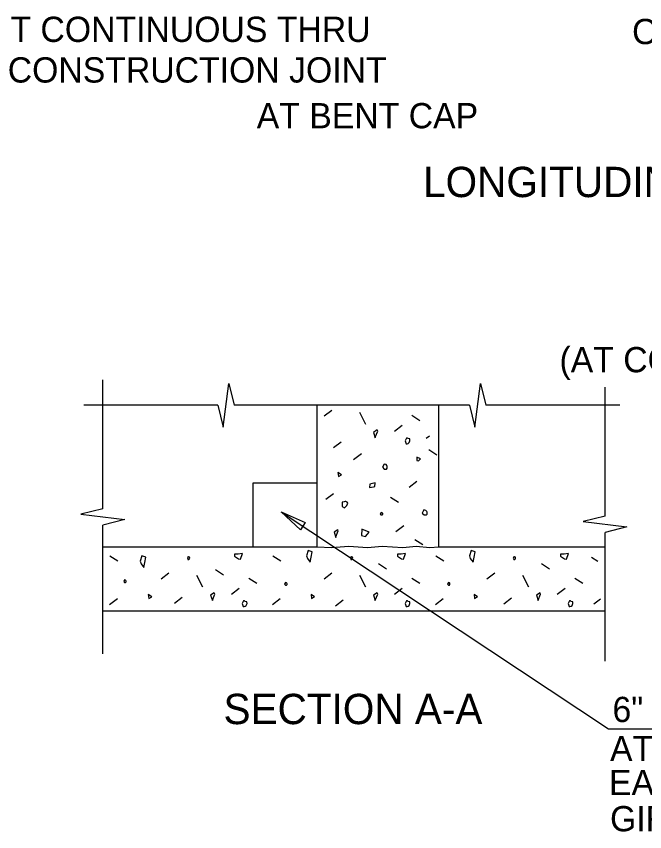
# Model space of a CAD drawing. Extents: x 0 to 34, y 0 to 23.5.
# Drawn here: x 12.66 to 16.55, y 10.5 to 15.54 of the extents above; entities that cross this region are included whole.
import ezdxf

# ---------------------------------------------------------------- set-up
doc = ezdxf.new("R2010")
doc.units = 0
for name, color, linetype in [('BRDG_ANNO_General-Notes', 7, 'Continuous'), ('BRDG_BASE_Obj-Line', 7, 'Continuous'), ('BRDG_BASE_Pattern', 7, 'Continuous')]:
    doc.layers.add(name, color=color, linetype=linetype)

msp = doc.modelspace()

# ---------------------------------------------------------------- linework, layer by layer
at = {"layer": 'BRDG_ANNO_General-Notes'}
for p, q in [((14.3009, 12.4781), (16.3274, 11.1383)), ((14.4196, 12.3676), (14.3009, 12.4781)), ((14.3009, 12.4781), (14.4491, 12.4121)), ((14.4491, 12.4121), (14.4196, 12.3676)), ((16.3274, 11.1383), (18.6193, 11.1383))]:
    msp.add_line(p, q, dxfattribs=at)
at = {"layer": 'BRDG_BASE_Obj-Line'}
for p, q in [((13.1971, 12.4985), (13.1971, 13.2941)), ((13.9423, 13.0021), (13.9762, 13.273)), ((13.9762, 13.273), (14.0101, 13.1376)), ((15.4996, 13.0021), (15.5335, 13.273)), ((15.5335, 13.273), (15.5673, 13.1376)), ((16.3054, 12.4532), (16.3054, 13.2488)), ((13.9085, 13.1376), (13.0791, 13.1376)), ((13.9085, 13.1376), (13.9423, 13.0021)), ((15.4658, 13.1376), (14.0101, 13.1376)), ((14.5242, 12.2626), (14.5242, 13.1376)), ((15.2762, 12.2626), (15.2762, 13.1376)), ((15.4658, 13.1376), (15.4996, 13.0021)), ((16.3968, 13.1376), (15.5673, 13.1376)), ((14.1283, 12.2626), (14.1283, 12.6584)), ((14.1283, 12.6584), (14.5242, 12.6584)), ((13.1971, 12.4985), (13.0617, 12.4646)), ((13.0617, 12.4646), (13.3326, 12.4308)), ((16.3054, 12.4532), (16.17, 12.4194)), ((13.3326, 12.4308), (13.1971, 12.3969)), ((16.17, 12.4194), (16.4408, 12.3855)), ((13.1971, 11.6014), (13.1971, 12.3969)), ((16.4408, 12.3855), (16.3054, 12.3517)), ((16.3054, 11.5561), (16.3054, 12.3517)), ((13.1971, 12.2626), (14.5242, 12.2626)), ((15.2762, 12.2626), (16.3054, 12.2626)), ((13.1971, 11.8667), (16.3054, 11.8667))]:
    msp.add_line(p, q, dxfattribs=at)
msp.add_lwpolyline([(14.5242, 12.2626), (14.6126, 12.258), (14.7205, 12.2667), (14.8354, 12.2576), (14.9259, 12.2662), (15.053, 12.258), (15.1366, 12.2671), (15.2202, 12.258), (15.2762, 12.2626)], dxfattribs=at)
at = {"layer": 'BRDG_BASE_Pattern'}
for p, q in [((14.6143, 13.1064), (14.5661, 13.0697)), ((14.7858, 13.0953), (14.8225, 13.0217)), ((15.1097, 13.0757), (15.1592, 13.0445)), ((15.0492, 13.0126), (15.0011, 12.976)), ((14.6726, 12.9107), (14.6245, 12.8741)), ((15.2187, 12.9472), (15.1982, 12.9316)), ((15.2139, 12.8636), (15.2634, 12.8324)), ((14.7969, 12.8367), (14.7487, 12.8001)), ((15.1406, 12.6665), (15.0925, 12.6298)), ((14.6243, 12.59), (14.5777, 12.5545)), ((14.9776, 12.5704), (15.0271, 12.5392)), ((15.0595, 12.3917), (15.0114, 12.3551)), ((15.1284, 12.3085), (15.178, 12.2772)), ((13.2403, 12.2078), (13.2897, 12.1765)), ((14.2486, 12.2078), (14.2981, 12.1765)), ((15.257, 12.2078), (15.3065, 12.1765)), ((16.2202, 12.1995), (16.2602, 12.1742)), ((14.9033, 12.1587), (14.9528, 12.1274)), ((15.9117, 12.1587), (15.9612, 12.1274)), ((13.6059, 12.099), (13.5578, 12.0624)), ((13.8949, 12.1217), (13.9444, 12.0904)), ((14.6143, 12.099), (14.5661, 12.0624)), ((15.6227, 12.099), (15.5745, 12.0624)), ((13.7774, 12.0879), (13.8141, 12.0144)), ((14.1013, 12.0684), (14.1508, 12.0371)), ((14.7858, 12.0879), (14.8225, 12.0144)), ((15.1097, 12.0684), (15.1592, 12.0371)), ((15.7942, 12.0879), (15.8309, 12.0144)), ((16.1181, 12.0684), (16.1676, 12.0371)), ((14.0408, 12.0053), (13.9927, 11.9686)), ((15.0492, 12.0053), (15.0011, 11.9686)), ((16.0576, 12.0053), (16.0095, 11.9686)), ((13.6889, 11.9486), (13.6407, 11.912)), ((13.2871, 11.9403), (13.239, 11.9036)), ((14.2955, 11.9403), (14.2473, 11.9036)), ((14.6849, 11.9321), (14.6368, 11.8955)), ((15.3039, 11.9403), (15.2557, 11.9036)), ((15.7263, 11.9445), (15.6781, 11.9079)), ((16.2766, 11.9392), (16.2353, 11.9078))]:
    msp.add_line(p, q, dxfattribs=at)
for points in [[(14.8719, 12.9705), (14.8833, 12.9372), (14.8833, 12.9408), (14.898, 12.9778), (14.8942, 12.9852)], [(15.0685, 12.9187), (15.0743, 12.9003), (15.0796, 12.9003), (15.0871, 12.9021), (15.0926, 12.9075), (15.0979, 12.9187), (15.0964, 12.9297), (15.0871, 12.9316), (15.0832, 12.9354), (15.0759, 12.9354)], [(15.1402, 12.8163), (15.1393, 12.7965), (15.1512, 12.7937), (15.1628, 12.8071)], [(14.9372, 12.7747), (14.928, 12.7545), (14.9388, 12.7432), (14.952, 12.7432), (14.9574, 12.7491), (14.9574, 12.7599), (14.9556, 12.7652), (14.9499, 12.7711)], [(14.6524, 12.7228), (14.6561, 12.6969), (14.6746, 12.708)], [(14.8503, 12.6511), (14.8466, 12.6291), (14.8724, 12.6328), (14.8797, 12.6364), (14.8834, 12.6585)], [(14.679, 12.5397), (14.679, 12.5118), (14.6917, 12.5028), (14.6955, 12.5064), (14.7064, 12.5175), (14.7137, 12.5323), (14.7084, 12.5397), (14.701, 12.5432), (14.6974, 12.5432), (14.6902, 12.5412)], [(14.9188, 12.4753), (14.9142, 12.4652), (14.9196, 12.4596), (14.9262, 12.4596), (14.9289, 12.4625), (14.9289, 12.4679), (14.928, 12.4706), (14.9252, 12.4735)], [(15.1833, 12.4909), (15.174, 12.4707), (15.1848, 12.4595), (15.1981, 12.4595), (15.2035, 12.4654), (15.2035, 12.4761), (15.2017, 12.4815), (15.1959, 12.4874)], [(14.6283, 12.3538), (14.6397, 12.3206), (14.6397, 12.3242), (14.6544, 12.3612), (14.6506, 12.3685)], [(14.7996, 12.3714), (14.7978, 12.3318), (14.8217, 12.3262), (14.8447, 12.353)], [(13.4395, 12.2072), (13.4283, 12.1741), (13.434, 12.1576), (13.4505, 12.1354), (13.4579, 12.1649), (13.4634, 12.1981)], [(13.7205, 12.1929), (13.7234, 12.1837), (13.726, 12.1837), (13.7298, 12.1846), (13.7325, 12.1873), (13.7352, 12.1929), (13.7344, 12.1984), (13.7298, 12.1994), (13.7278, 12.2013), (13.7242, 12.2013)], [(14.0347, 12.2182), (14.0126, 12.2164), (14.0126, 12.2053), (14.0366, 12.1888), (14.0495, 12.1869), (14.0624, 12.2219)], [(14.4684, 12.2402), (14.4572, 12.207), (14.4629, 12.1905), (14.4795, 12.1683), (14.4868, 12.1978), (14.4923, 12.231)], [(14.7289, 12.1929), (14.7318, 12.1837), (14.7344, 12.1837), (14.7382, 12.1846), (14.7409, 12.1873), (14.7435, 12.1929), (14.7428, 12.1984), (14.7382, 12.1994), (14.7362, 12.2013), (14.7326, 12.2013)], [(15.0431, 12.2182), (15.021, 12.2164), (15.021, 12.2053), (15.0449, 12.1888), (15.0579, 12.1869), (15.0708, 12.2219)], [(15.4768, 12.2402), (15.4656, 12.207), (15.4713, 12.1905), (15.4879, 12.1683), (15.4952, 12.1978), (15.5007, 12.231)], [(15.7372, 12.1929), (15.7402, 12.1837), (15.7428, 12.1837), (15.7466, 12.1846), (15.7493, 12.1873), (15.7519, 12.1929), (15.7512, 12.1984), (15.7466, 12.1994), (15.7446, 12.2013), (15.7409, 12.2013)], [(16.0515, 12.2182), (16.0294, 12.2164), (16.0294, 12.2053), (16.0533, 12.1888), (16.0663, 12.1869), (16.0792, 12.2219)], [(13.3309, 12.0587), (13.3262, 12.0486), (13.3317, 12.043), (13.3383, 12.043), (13.341, 12.0459), (13.341, 12.0514), (13.3401, 12.054), (13.3372, 12.057)], [(14.3269, 12.0423), (14.3223, 12.0321), (14.3277, 12.0265), (14.3343, 12.0265), (14.337, 12.0295), (14.337, 12.0349), (14.3361, 12.0376), (14.3333, 12.0405)], [(15.3353, 12.0423), (15.3307, 12.0321), (15.3361, 12.0265), (15.3427, 12.0265), (15.3454, 12.0295), (15.3454, 12.0349), (15.3445, 12.0376), (15.3417, 12.0405)], [(13.4774, 11.9685), (13.4811, 11.9427), (13.4996, 11.9538)], [(13.8635, 11.9631), (13.8749, 11.9299), (13.8749, 11.9335), (13.8896, 11.9705), (13.8858, 11.9778)], [(14.4858, 11.9685), (14.4895, 11.9427), (14.508, 11.9538)], [(14.8719, 11.9631), (14.8833, 11.9299), (14.8833, 11.9335), (14.898, 11.9705), (14.8942, 11.9778)], [(15.4942, 11.9685), (15.4979, 11.9427), (15.5164, 11.9538)], [(15.8803, 11.9631), (15.8917, 11.9299), (15.8917, 11.9335), (15.9064, 11.9705), (15.9026, 11.9778)], [(14.0601, 11.9114), (14.0659, 11.893), (14.0712, 11.893), (14.0787, 11.8948), (14.0842, 11.9002), (14.0895, 11.9114), (14.088, 11.9223), (14.0787, 11.9243), (14.0748, 11.9281), (14.0675, 11.9281)], [(15.0685, 11.9114), (15.0743, 11.893), (15.0796, 11.893), (15.0871, 11.8948), (15.0926, 11.9002), (15.0979, 11.9114), (15.0964, 11.9223), (15.0871, 11.9243), (15.0832, 11.9281), (15.0759, 11.9281)], [(16.0769, 11.9114), (16.0827, 11.893), (16.088, 11.893), (16.0955, 11.8948), (16.1009, 11.9002), (16.1063, 11.9114), (16.1048, 11.9223), (16.0955, 11.9243), (16.0916, 11.9281), (16.0843, 11.9281)]]:
    msp.add_lwpolyline(points, close=True, dxfattribs=at)

# ---------------------------------------------------------------- texts
at = {"layer": 'BRDG_ANNO_General-Notes'}
for s, height, p in [('REINFORCEMENT CONTINUOUS THRU', 0.15625, (10.9307, 15.384)), ('OVER 50% OF AREA', 0.15625, (16.4729, 15.3705)), ('CONSTRUCTION JOINT', 0.15625, (12.6088, 15.133)), ('AT BENT CAP', 0.15625, (14.1497, 14.8502)), ('LONGITUDINAL CONSTRUCTION JOINTS', 0.1875, (15.1789, 14.4248)), ("(AT CONTRACTOR'S OPTION)", 0.15625, (16.0231, 13.3418)), ('SECTION A-A', 0.1875, (13.9441, 11.1665)), ('6" SQUARE DRAIN', 0.15625, (16.351, 11.1791)), ('AT LOW SIDE OF', 0.15625, (16.336, 10.9376)), ('EACH BAY BETWEEN', 0.15625, (16.3296, 10.7275)), ('GIRDERS.', 0.15625, (16.336, 10.5038))]:
    msp.add_text(s, height=height, dxfattribs=at).set_placement(p)

doc.saveas('drawing.dxf')
